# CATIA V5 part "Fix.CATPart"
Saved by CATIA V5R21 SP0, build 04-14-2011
Part number: Part1
Bounding box of the stored display mesh (mm): x -20 to 0, y -45 to 45, z -45 to 45
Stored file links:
  E:\cadcim\Projects\CATIA V5-6R2015_Menuscript\WebResources\CATIA V5-6r2015_partfiles\Partfiles\c16_catia_v5_6r2015_prt\Cable Joint - (Fig16-60)\Fix.CATPart
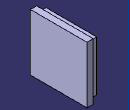
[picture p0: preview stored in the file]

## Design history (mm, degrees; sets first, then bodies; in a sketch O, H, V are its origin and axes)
Body1 (main body)
  Sketch1 on yz-plane, origin (0, 0, 0), H (0, 1, 0), V (0, 0, 1)
    line L1 (40, 40) -> (40, -40)
    line L2 (40, -40) -> (-40, -40)
    line L3 (-40, -40) -> (-40, 40)
    line L4 (-40, 40) -> (40, 40)
    line L5 (45, 45) -> (45, -45)
    line L6 (45, -45) -> (-45, -45)
    line L7 (-45, -45) -> (-45, 45)
    line L8 (-45, 45) -> (45, 45)
    length L4 = 80
    length L1 = 80
    length L5 = 90
    length L8 = 90
    vertical: L1 V, L3 V, L5 V, L7 V
    horizontal: L2 H, L4 H, L6 H, L8 H
    equidistance: L1 L3 O, L2 L4 O, L5 L7 O, L6 L8 O
  MultiPad1: profile Sketch1, domains (length 10; length 20)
